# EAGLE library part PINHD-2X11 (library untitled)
PIN HEADER
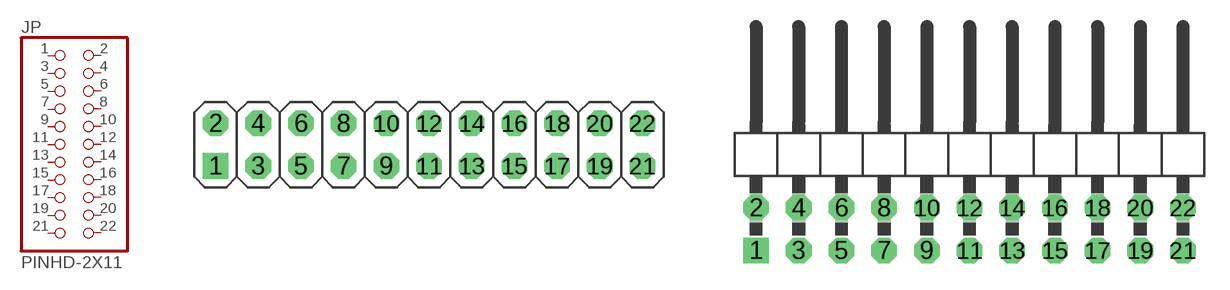
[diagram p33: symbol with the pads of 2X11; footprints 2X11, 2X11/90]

Designator prefix JP

## PINHD-2X11_2.54  [2X11]
1  1  pas
2  2  pas
3  3  pas
4  4  pas
5  5  pas
6  6  pas
7  7  pas
8  8  pas
9  9  pas
10  10  pas
11  11  pas
12  12  pas
13  13  pas
14  14  pas
15  15  pas
16  16  pas
17  17  pas
18  18  pas
19  19  pas
20  20  pas
21  21  pas
22  22  pas

## PINHD-2X11_2.54-90°  [2X11/90]
Pads as for 2X11

## PINHD-2X11_2.00  [2X11M]
Pads as for 2X11

## PINHD-2X11_2.54-SMD  [2X11SMD]
Pads as for 2X11

## PINHD-2X11_2.54-SMD-90°  [2X11SMD/90]
Pads as for 2X11

## Footprint 2X11 (pad centres in mm)
PIN HEADER - 2.54
drill 1.016 square: 1 -12.7,-1.27
drill 1.016 octagon: 2 -12.7,1.27; 3 -10.16,-1.27; 4 -10.16,1.27; 5 -7.62,-1.27; 6 -7.62,1.27; 7 -5.08,-1.27; 8 -5.08,1.27; 9 -2.54,-1.27; 10 -2.54,1.27; 11 0,-1.27; 12 0,1.27; 13 2.54,-1.27; 14 2.54,1.27; 15 5.08,-1.27; 16 5.08,1.27; 17 7.62,-1.27; 18 7.62,1.27; 19 10.16,-1.27; 20 10.16,1.27; 21 12.7,-1.27; 22 12.7,1.27

## Footprint 2X11/90 (pad centres in mm)
PIN HEADER - 2.54 90°
drill 1.016 square: 1 -12.7,-6.35
drill 1.016 octagon: 2 -12.7,-3.81; 3 -10.16,-6.35; 4 -10.16,-3.81; 5 -7.62,-6.35; 6 -7.62,-3.81; 7 -5.08,-6.35; 8 -5.08,-3.81; 9 -2.54,-6.35; 10 -2.54,-3.81; 11 0,-6.35; 12 0,-3.81; 13 2.54,-6.35; 14 2.54,-3.81; 15 5.08,-6.35; 16 5.08,-3.81; 17 7.62,-6.35; 18 7.62,-3.81; 19 10.16,-6.35; 20 10.16,-3.81; 21 12.7,-6.35; 22 12.7,-3.81

## Footprint 2X11M (pad centres in mm)
PIN HEADER - 2
drill 0.914 square: 1 -10,-1
drill 0.914 round: 2 -10,1; 3 -8,-1; 4 -8,1; 5 -6,-1; 6 -6,1; 7 -4,-1; 8 -4,1; 9 -2,-1; 10 -2,1; 11 0,-1; 12 0,1; 13 2,-1; 14 2,1; 15 4,-1; 16 4,1; 17 6,-1; 18 6,1; 19 8,-1; 20 8,1; 21 10,-1; 22 10,1

## Footprint 2X11SMD (pad centres in mm)
PIN HEADER - 2.54 SMD
smd 1.016 x 3.302: 1 -1.27,-3.81; 2 -1.27,1.27; 3 1.27,-3.81; 4 1.27,1.27; 5 3.81,-3.81; 6 3.81,1.27; 7 6.35,-3.81; 8 6.35,1.27; 9 8.89,-3.81; 10 8.89,1.27; 11 11.43,-3.81; 12 11.43,1.27; 13 13.97,-3.81; 14 13.97,1.27; 15 16.51,-3.81; 16 16.51,1.27; 17 19.05,-3.81; 18 19.05,1.27; 19 21.59,-3.81; 20 21.59,1.27; 21 24.13,-3.81; 22 24.13,1.27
